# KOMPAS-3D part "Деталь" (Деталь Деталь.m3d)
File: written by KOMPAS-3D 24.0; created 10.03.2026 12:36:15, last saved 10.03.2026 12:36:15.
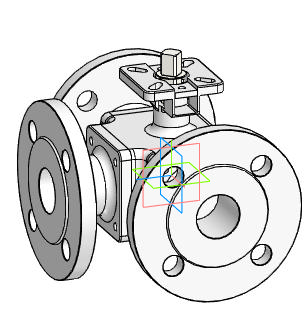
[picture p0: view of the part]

Document properties: Автор: R2D2; Полное имя файла: E:\Работа\Зайцев\BV3232P(4pc)-FP-3WL-F-ISO-H Кран шаровой DN.ru Ду15-100 Ру16\DN40\исходные материалы\Деталь Деталь.m3d

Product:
- Body: Твердое тело1  | qty 1
- Part/product: Деталь
    additional columns: Типовые

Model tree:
1. Твердое тело1  (labels: Твердое тело1)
